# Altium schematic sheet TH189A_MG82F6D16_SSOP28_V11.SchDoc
size 274 x 190 mm; PageSetup: Record=PageOptions|CenterHorizontal=True|CenterVertical=True|PrintScale=1.09|XCorrection=1.00|YCorrection=1.00|PrintKind=0|BorderSize=5000000|LeftOffset=0|BottomOffset=0|Orientation=2|PaperLength=1000|PaperWidth=1000|Scale=100|PaperSource=7|PrintQuality=-4|MediaType=1|DitherType=10|PaperKind=A4 (210 x 297 mm)|PrintScaleMode=1
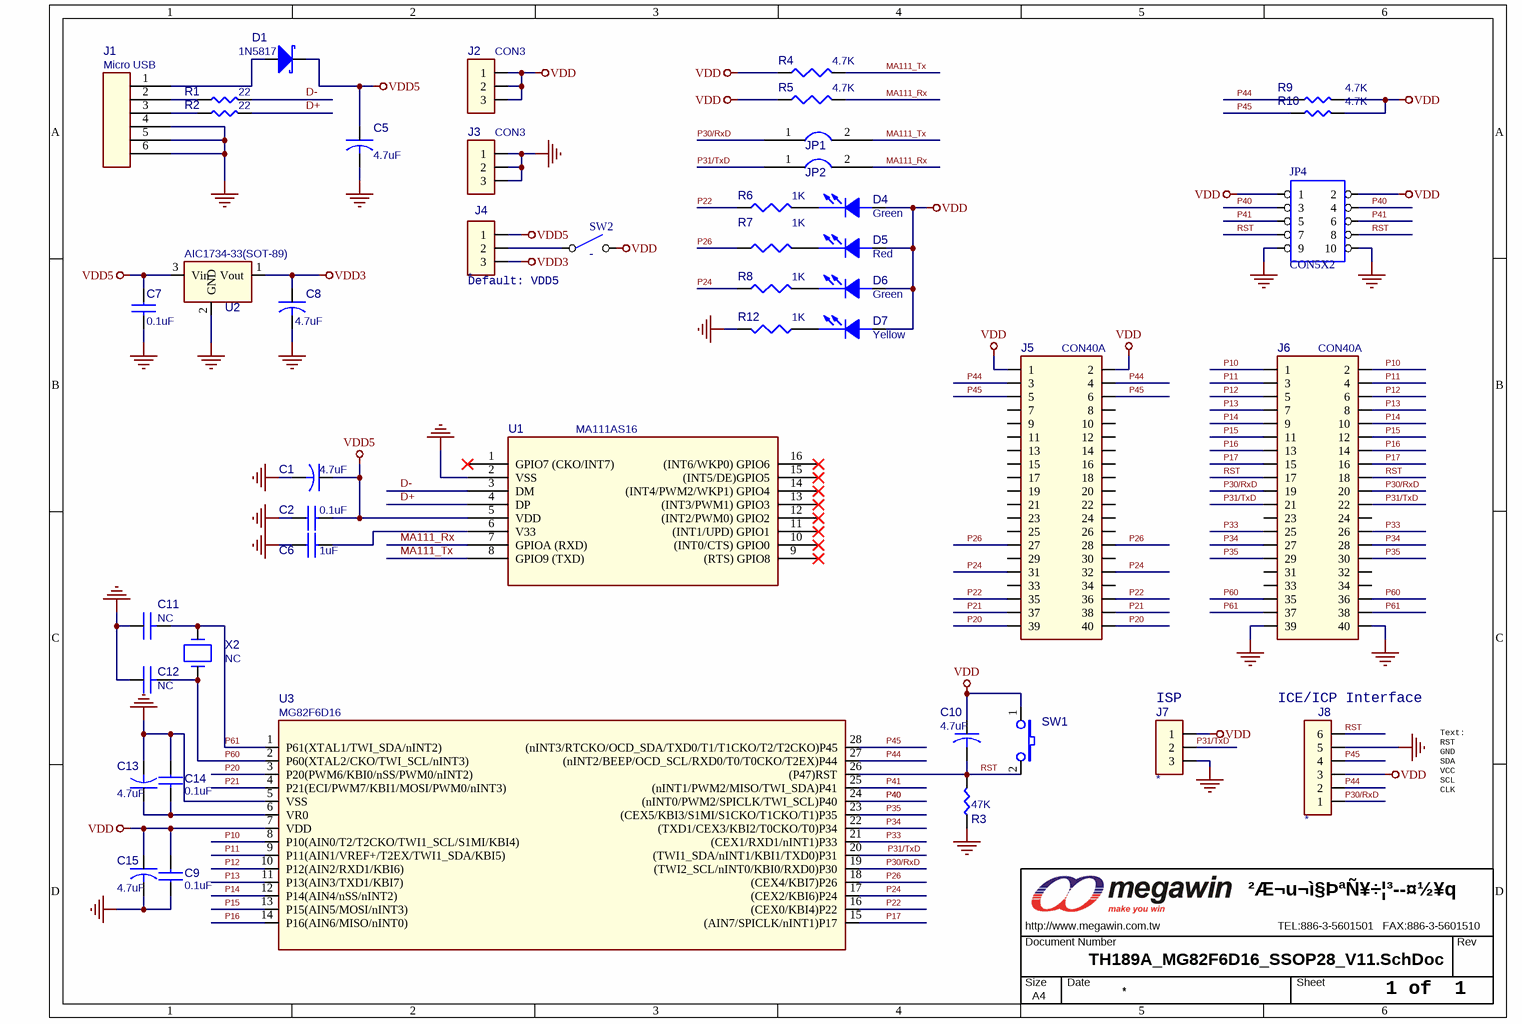
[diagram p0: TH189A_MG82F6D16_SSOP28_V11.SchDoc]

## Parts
C1  4.7uF  [0805C]
C2  0.1uF  [0805C]
C5  4.7uF  [0805C]
C6  1uF  [0805C]
C7  0.1uF  [0805C]
C8  4.7uF  [0805C]
C9  0.1uF  [0805C]
C10  4.7uF  [0805C]
C11  NC  [0805C]
C12  NC  [0805C]
C13  4.7uF  [0805C]
C14  0.1uF  [0805C]
C15  4.7uF  [0805C]
D1  1N5817  [DIODE_SMA]
D4  Green  [0805D]
D5  Red  [0805D]
D6  Green  [0805D]
D7  Yellow  [0805D]
J1  Micro USB  [JACK_USB_SMD290X220P065]
J2  CON3  [PS3P254]
J3  CON3  [PS3P254]
J4  *  [JUMP3_SMD]
J5  CON40A  [PS20X2P254]
J6  CON40A  [PS20X2P254]
J7  *  [PS3P254f_90]
J8  *  [PS6P254F_90]
JP1  JUMPER2  [PS2P254]  (value not drawn)
JP2  JUMPER2  [PS2P254]  (value not drawn)
JP4  CON5X2  [PS5X2P254]
MW1  OrgAddr3: TEL:886-3-5601501   FAX:886-3-5601510  Page Size: A4  [MEGAWIN10_1]  (hidden comment: MW-A4)  (graphical)
R1  22  [0805R]
R2  22  [0805R]
R3  47K  [0805R]
R4  4.7K  [0805R]
R5  4.7K  [0805R]
R6  1K  [0805R]
R7  1K  [0805R]
R8  1K  [0805R]
R9  4.7K  [0805R]
R10  4.7K  [0805R]
R12  1K  [0805R]
SW1  SW TACT-SPST  [SW_T_2P]  (value not drawn)
SW2  -  [DIP2_SW]
U1  MA111AS16  [SO16_150P127]
U2  AIC1734-33(SOT-89)  [SOT89]
U3  MG82F6D16  [SSOP28_150P0635]
X2  NC  [X49U]

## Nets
GND_POWER: C1.2 C2.1 C5.2 C6.1 C7.2 C8.2 C9.1 C11.1 C12.1 C13.2 C14.1 C15.2 J1.4 J1.5 J1.6 J3.1 J3.2 J3.3 J6.39 J6.40 J7.3 J8.5 JP4.9 JP4.10 R3.1 R12.1 U1.2(VSS) U2.2(GND) U3.5(VSS)
VDD: C9.2 C10.1(POS) C15.1 D4.1(ANODE) D5.1(ANODE) D6.1(ANODE) D7.1(ANODE) J2.1 J2.2 J2.3 J5.1 J5.2 J7.1 J8.3 JP4.1 JP4.2 R4.1 R5.1 R9.2 R10.2 SW1.1 SW2.2(NO) U3.7(VDD)
VDD3: C8.1 J4.3 U2.1(Vout)
VDD5: C1.1 C2.2 C5.1 C7.1 D1.2(K) J4.1 U1.5(VDD) U2.3(Vin)
D+: R2.2 U1.4(DP)
D-: R1.2 U1.3(DM)
MA111_Rx: JP2.2 R5.2 U1.7(GPIOA_(RXD))
MA111_Tx: JP1.2 R4.2 U1.8(GPIO9_(TXD))
P10: J6.1 J6.2 U3.8(P10(AIN0/T2/T2CKO/TWI1_SCL/S1MI/KBI4))
P11: J6.3 J6.4 U3.9(P11(AIN1/VREF+/T2EX/TWI1_SDA/KBI5))
P12: J6.5 J6.6 U3.10(P12(AIN2/RXD1/KBI6))
P13: J6.7 J6.8 U3.11(P13(AIN3/TXD1/KBI7))
P14: J6.9 J6.10 U3.12(P14(AIN4/nSS/nINT2))
P15: J6.11 J6.12 U3.13(P15(AIN5/MOSI/nINT3))
P16: J6.13 J6.14 U3.14(P16(AIN6/MISO/nINT0))
P17: J6.15 J6.16 U3.15((AIN7/SPICLK/nINT1)P17)
P20: J5.39 J5.40 U3.3(P20(PWM6/KBI0/nSS/PWM0/nINT2))
P21: J5.37 J5.38 U3.4(P21(ECI/PWM7/KBI1/MOSI/PWM0/nINT3))
P22: J5.35 J5.36 R6.1 U3.16((CEX0/KBI4)P22)
P24: J5.31 J5.32 R8.1 U3.17((CEX2/KBI6)P24)
P26: J5.27 J5.28 R7.1 U3.18((CEX4/KBI7)P26)
P30/RxD: J6.19 J6.20 J8.1 JP1.1 U3.19((TWI2_SCL/nINT0/KBI0/RXD0)P30)
P31/TxD: J6.21 J6.22 J7.2 JP2.1 U3.20((TWI1_SDA/nINT1/KBI1/TXD0)P31)
P33: J6.25 J6.26 U3.21((CEX1/RXD1/nINT1)P33)
P34: J6.27 J6.28 U3.22((TXD1/CEX3/KBI2/T0CKO/T0)P34)
P35: J6.29 J6.30 U3.23((CEX5/KBI3/S1MI/S1CKO/T1CKO/T1)P35)
P40: JP4.3 JP4.4 U3.24((nINT0/PWM2/SPICLK/TWI_SCL)P40)
P41: JP4.5 JP4.6 U3.25((nINT1/PWM2/MISO/TWI_SDA)P41)
P44: J5.3 J5.4 J8.2 R9.1 U3.27((nINT2/BEEP/OCD_SCL/RXD0/T0/T0CKO/T2EX)P44)
P45: J5.5 J5.6 J8.4 R10.1 U3.28((nINT3/RTCKO/OCD_SDA/TXD0/T1/T1CKO/T2/T2CKO)P45)
P60: C12.2 J6.35 J6.36 U3.2(P60(XTAL2/CKO/TWI_SCL/nINT3)) X2.2
P61: C11.2 J6.37 J6.38 U3.1(P61(XTAL1/TWI_SDA/nINT2)) X2.1
RST: C10.2(NEG) J6.17 J6.18 J8.6 JP4.7 JP4.8 R3.2 SW1.2 U3.26((P47)RST)
NetC6_2: C6.2 U1.6(V33)
NetC13_1: C13.1 C14.2 U3.6(VR0)
NetD1_1: D1.1(A) J1.1
NetD4_2: D4.2(CATHODE) R6.2
NetD5_2: D5.2(CATHODE) R7.2
NetD6_2: D6.2(CATHODE) R8.2
NetD7_2: D7.2(CATHODE) R12.2
NetJ1_2: J1.2 R1.1
NetJ1_3: J1.3 R2.1
NetJ4_2: J4.2 SW2.1(COMMON)

Not connected (* = marked no-connect by the designer): J5 7 8 9 10 11 12 13 14 15 16 17 18 19 20 21 22 23 24 25 26 29 30 33 34; J6 23 24 31 32 33 34; U1 1(GPIO7_(CKO/INT7))* 9((RTS)_GPIO8)* 10((INT0/CTS)_GPIO0)* 11((INT1/UPD)_GPIO1)* 12((INT2/PWM0)_GPIO2)* 13((INT3/PWM1)_GPIO3)* 14((INT4/PWM2/WKP1)_GPIO4)* 15((INT5/DE)GPIO5)* 16((INT6/WKP0)_GPIO6)*

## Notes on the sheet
- (near J4) Default: VDD5
- (near J7) ISP
- (near J8) ICE/ICP Interface
- Text:
  RST
  GND
  SDA
  VCC
  SCL
  CLK
- 1 of  1

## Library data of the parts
C1 C5 C8 C13 C15 = CAP
C2 C6 C7 C9 C14 = CAP NP
C10 = C
C11 C12 = C NP
D1 = DIODE_ZD: Schottky Diode
D4-D7 = LED
J1 J8 = CON6
J4 J7 = CON3
MW1 = MW_A4
R1-R3 R9 R10 = R
R4-R8 = R_Dup1
R12 = R_Dup2
SW2 = SW-2
U2 = AIC1734-33(SOT-89)_0
U3 = MG82FG5Dxx_SSOP-28
X2 = CRYSTAL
